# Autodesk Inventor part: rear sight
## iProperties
Created: 2006-04
Part Number: rear sight
Document SubType Name: Modeling
Designer: Калинин
Author: Калинин
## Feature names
1. Выдавливание1 [Extrusion]
2. Фаска1 [Chamfer]
3. Сопряжение1 [Fillet]
